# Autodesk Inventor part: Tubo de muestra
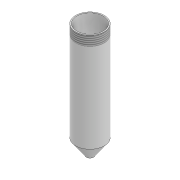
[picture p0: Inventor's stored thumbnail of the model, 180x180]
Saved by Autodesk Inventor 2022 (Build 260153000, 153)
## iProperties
Created: 2022-02
Part Number: Tubo de muestra
Material: Genérico
Document SubType Name: Modeling
Designer: Juan David
Density: 1 g/cm^3
Appearance: Valor por defecto
Author: Juan David
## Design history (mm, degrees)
sketch "Boceto1"
  geometry: L1 (0, 0)-(0, 116.5); L2 (0, 116.5)-(14.5, 116.5); L3 (14.5, 116.5)-(14.5, 16.5); L4 (0, 0)-(3, 0); L5 (3, 0)-(14.5, 16.5); L6 (0, 0)-(0, 116.5)
  constraints: 12 end point, 2 perpendicular, 1 collinear, 1 horizontal, 1 vertical
  dimensions: "d0" = 116.5 distance of L1.start L1.end; "d1" = 14.5 distance of L1.end L2.end; "d2" = 100 distance of L2.end L3.end; "d3" = 3 distance of L1.start L4.end
revolve "Revolución1" sketch "Boceto1" stored, may be unused: angle "d4" = 90 deg
feature "Vaciado1" dims "d5" = 1.2
feature "Rosca1" dims "d6" = 10, "d7" = 0
fillet "Empalme1" dims "d8" = 3
node "Sólido1"
